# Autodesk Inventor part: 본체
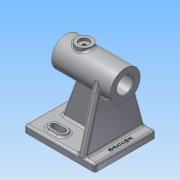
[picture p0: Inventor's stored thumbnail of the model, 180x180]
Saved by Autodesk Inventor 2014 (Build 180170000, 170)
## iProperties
Created: 2019-10
Part Number: 본체
Material: 알루미늄 6061
Document SubType Name: Modeling
Designer: net
Density: 2.71 g/cm^3
Appearance: 알루미늄 - 평지
Mass: 589.386 g
Surface Area: 543.417 cm^2
Volume: 217.486 cm^3
Author: net
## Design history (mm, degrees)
node "작업 평면1"
sketch "스케치4"
  geometry: L1 (-50, -43)-(50, -43); L2 (50, -43)-(50, 43); L3 (50, 43)-(-50, 43); L4 (-50, 43)-(-50, -43); L5 (-50, -43)-(50, 43); L6 (50, -43)-(-50, 43); 1 further point
  constraints: 12 end point, 2 midpoint, 2 parallel, 1 horizontal, 1 perpendicular
  dimensions: "d26" = 100 distance of L2.end L3.end; "d27" = 86 distance of L1.end L2.end
extrude "돌출1" join sketch "스케치4" distance "d28" = 10; taper "d29" = 0 deg
sketch "스케치5"
  geometry: L1 (50, -43)-(50, 43) reference; L2 (50, 0)-(50, 27); L3 (50, 27)-(24, 27); L4 (24, 27)-(12, 27); L5 (12, 31.5)-(24, 31.5); L6 (24, 22.5)-(12, 22.5); L7 (12, 27)-(12, 34); L8 (24, 27)-(24, 34); L9 (24, 34)-(12, 34); L10 (12, 20)-(24, 20); L11 (24, 20)-(12, 20); A1 r 4.5 centre (24, 27) between (24, 22.5) and (24, 31.5); A2 r 4.5 centre (12, 27) between (12, 31.5) and (12, 22.5); A3 r 7 centre (24, 27) between (24, 20) and (24, 34); A4 r 7 centre (12, 27) between (12, 34) and (12, 20); 1 further point
  constraints: 20 end point, 8 point on circle, 5 tangent, 4 centre point, 4 coincident, 3 perpendicular, 1 collinear, 1 midpoint, 1 parallel, 1 point on line
  dimensions: "d30" = 27 distance of L2.start L2.end; "d31" = 26 distance of L2.end L3.end; "d32" = 9 diameter of A1; "d33" = 12 distance of L4.start L4.end; "d34" = 9 diameter of A2; "d35" = 7 distance of L7.start L7.end; "d36" = 7 distance of L7.start L10.start; "d37" = 7 distance of L4.start L8.end
extrude "돌출2" join sketch "스케치5" distance "d38" = 3; taper "d39" = 0 deg
extrude "돌출3" cut sketch "스케치5" stored distance "d40" = 3; taper "d41" = 0 deg
sketch "스케치6"
  geometry: L1 (24, -22.5)-(12, -22.5) reference; L2 (12, -31.5)-(24, -31.5) reference; L3 (24, -31.5)-(12, -31.5); L4 (12, -22.5)-(24, -22.5); A1 r 4.5 centre (24, -27) between (24, -31.5) and (24, -22.5) reference; A2 r 4.5 centre (12, -27) between (12, -22.5) and (12, -31.5) reference; A3 r 4.5 centre (12, -27) between (12, -22.5) and (12, -31.5); A4 r 4.5 centre (24, -27) between (24, -31.5) and (24, -22.5); 1 further point
  constraints: 8 tangent, 4 end point, 4 point on circle, 2 centre point, 2 coincident, 2 collinear
extrude "돌출4" cut sketch "스케치6" stored distance "d42" = 3; taper "d43" = 0 deg
fillet "모깎기3" dims "d56" = 3
fillet "모깎기4" dims "d57" = 3
fillet "모깎기5" dims "d58" = 3
sketch "스케치18"
  geometry: L1 (47, 43)-(-47, 43) reference; L2 (-47, -43)-(47, -43) reference; L3 (-50, 40)-(-50, -40) reference; 4 further points
  constraints: 1 other
  dimensions: "d84" = 43 distance from line of L1 point (-43, 0); "d85" = 7 distance from line of L3 point (-43, 0)
feature "엠보싱1" sketch "스케치18" dims "d26" = 100, "d27" = 86, "d86" = 0.5, "d87" = 0
sketch "스케치19"
  geometry: L1 (32, 0)-(-50, 0); L2 (-47, 86)-(47, 86) reference; L3 (-50, -11.5)-(-28.698, -11.5); L4 (-28.698, -11.5)-(-28.698, -14.5); L5 (-28.698, -14.5)-(33.302, -14.5); L6 (33.302, -14.5)-(33.302, -21); L7 (33.302, -21)-(-50, -21); L8 (-50, -21)-(-50, -11.5); 2 further points
  constraints: 14 end point, 4 parallel, 2 perpendicular, 1 horizontal, 1 vertical alignment
  dimensions: "d89" = 82 distance of L1.start L1.end; "d90" = 86 distance between parallel lines of L2 L1; "d91" = 23 diameter of L3 L1; "d92" = 42 diameter of L7 L1; "d93" = 62 distance of L4.end L5.end; "d94" = 29 diameter of L5 L1
revolve "회전2" sketch "스케치19" stored, may be unused: angle "d95" = 90 deg
chamfer "모따기2" distance "d96" = 1; stored, may be unused: second distance "d97" = 2, angle "d98" = 45 deg
sketch "스케치20"
  geometry: C1 r 12.5 at (0, 0) reference; A1 r 18 centre (0, 0) between (0, 18) and (18, 0); 2 further points
  constraints: 4 point on circle, 1 centre point, 1 coincident
  dimensions: "d99" = 36 diameter of A1
hole "구멍4" sketch "스케치20" at (0, 18), (18, 0), (0, -18), (-18, 0) diameter "d100" = 2.459; stored, may be unused: countersink angle "d104" = 90 deg, drill point angle "d106" = 118 deg; dims "d101" = 8, "d102" = 4, "d103" = 2, "d105" = 10
sketch "스케치21"
  geometry: C1 r 15.5 at (0, 0) reference; A1 r 18 centre (0, 0) between (0, 18) and (18, 0); 2 further points
  constraints: 4 point on circle, 1 centre point, 1 coincident
  dimensions: "d107" = 36 diameter of A1
hole "구멍5" sketch "스케치21" at (0, 18), (18, 0), (0, -18), (-18, 0) diameter "d108" = 2.459; stored, may be unused: countersink angle "d112" = 90 deg, drill point angle "d114" = 118 deg; dims "d109" = 8, "d110" = 4, "d111" = 2, "d113" = 10
sketch "스케치22"
  geometry: L1 (50, 79)-(50, 86) reference; L2 (-47, 76)-(47, 76) reference; L3 (35, 76)-(14.109, 18.601); L4 (14.109, 18.601)-(-25, 18.601); L5 (-25, 18.601)-(-25, 76); L6 (35, 76)-(-25, 76); A1 r 3 centre (47, 79) between (47, 76) and (50, 79) reference; 1 further point
  constraints: 8 end point, 2 perpendicular, 2 point on line, 1 parallel
  dimensions: "d115" = 15 distance from line of L3.start L1; "d116" = 70 deg angle of L2 L3; "d117" = 75 distance from line of L1 L5.end
extrude "돌출11" join sketch "스케치22" stored distance "d118" = 10; taper "d119" = 0 deg
sketch "스케치23"
  geometry: L1 (-76, 5)-(-20.396, 5) reference; L2 (-76, -5)-(-76, 5) reference; L3 (-20.396, -5)-(-76, -5) reference; L4 (-79, -43)-(-86, -43) reference; L5 (-76, 40)-(-76, -40) reference; L6 (-86, 43)-(-79, 43) reference; L7 (-76, 17)-(-76, 37) reference; L8 (-79, -43)-(5.456, -20.279); L9 (-79, 43)-(5.456, 20.279); L10 (-79, -43)-(-79, 43); A1 r 21 centre (0, 0) between (-20.396, 5) and (-20.396, -5) reference; A2 r 3 centre (-79, -40) between (-79, -43) and (-76, -40) reference; A3 r 3 centre (-79, 40) between (-76, 40) and (-79, 43) reference; A4 r 21 centre (0, 0) between (-20.396, -5) and (-20.396, 5) reference; 1 further point
  constraints: 6 end point, 3 point on circle, 2 tangent, 1 coincident, 1 perpendicular, 3 other
extrude "돌출12" join sketch "스케치23" distance "d120" = 10; taper "d121" = 0 deg
fillet "모깎기8" dims "d122" = 3
fillet "모깎기9" dims "d123" = 3
fillet "모깎기10" dims "d124" = 3
node "작업 평면4"
sketch "스케치24"
  geometry: L1 (33.302, 21)-(33.302, -21) reference; L2 (33.302, 0)-(8.302, 0); C1 r 11 at (8.302, 0); 1 further point
  constraints: 2 end point, 1 centre point, 1 coincident, 1 midpoint, 1 perpendicular
  dimensions: "d126" = 25 distance of L2.start L2.end; "d127" = 22 diameter of C1
extrude "돌출13" join sketch "스케치24" stored distance "d128" = 10; taper "d129" = 0 deg
sketch "스케치25"
  geometry: C1 r 11 at (0, 0) reference; C2 r 7 at (0, 0); 1 further point
  constraints: 1 centre point, 1 coincident
  dimensions: "d130" = 14 diameter of C2
extrude "돌출14" cut sketch "스케치25" distance "d131" = 4; taper "d132" = 0 deg
sketch "스케치26"
  geometry: C1 r 7 at (0, 0) reference; 2 further points
  constraints: 1 coincident
hole "구멍6" sketch "스케치26" at (0, 0) diameter "d133" = 4.917; stored, may be unused: countersink angle "d137" = 90 deg, drill point angle "d139" = 118 deg; dims "d134" = 15, "d135" = 4, "d136" = 2, "d138" = 20
fillet "모깎기11" dims "d140" = 3
sketch "스케치27"
  geometry: 1 further point
node "솔리드1"
mirror "대칭1"
other parameters: "d25" = 86
